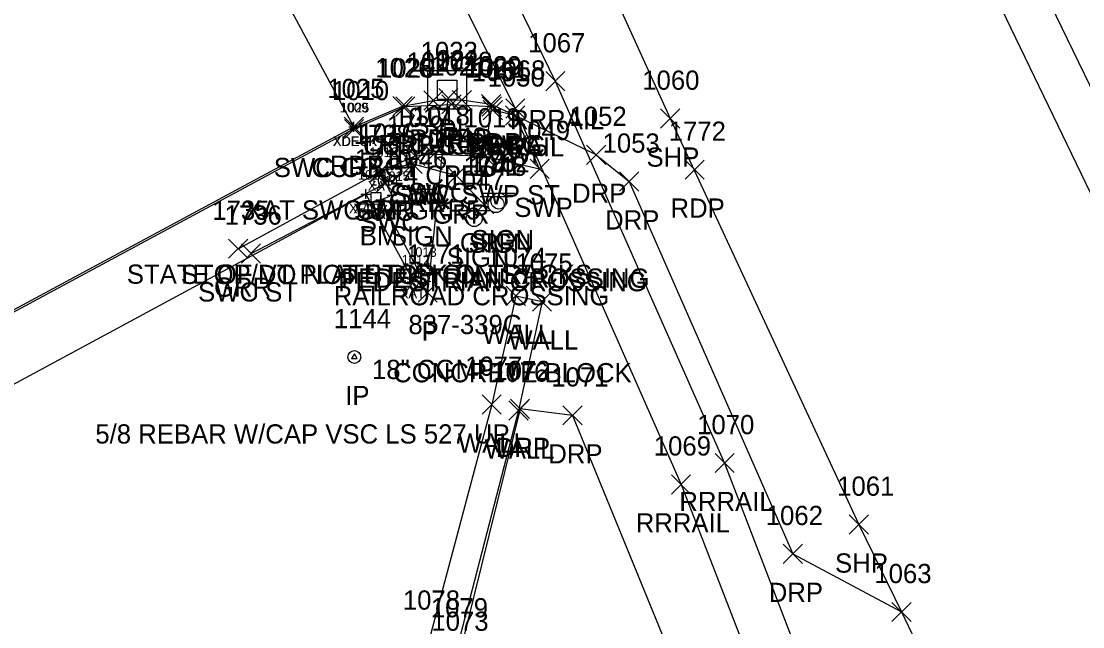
# Model space of a CAD drawing. Extents: x 1635588 to 1637550, y 621583 to 623638.
# Drawn here: x 1636369.1 to 1636479.5, y 623114.4 to 623177.4 of the extents above; entities that cross this region are included whole.
import ezdxf

# ---------------------------------------------------------------- set-up
doc = ezdxf.new("R2010")
doc.units = 0
for name, color, linetype in [('B_A', 7, 'Continuous'), ('B_I', 7, 'Continuous'), ('B_TIC', 7, 'Continuous'), ('BELB', 7, 'Continuous'), ('BF', 7, 'Continuous'), ('BSUBM', 7, 'Continuous'), ('C_A', 7, 'Continuous'), ('C_C', 7, 'Continuous'), ('C_I', 7, 'Continuous'), ('CPBM', 7, 'Continuous'), ('D_A', 7, 'Continuous'), ('D_C', 7, 'Continuous'), ('D_I', 7, 'Continuous'), ('D_TIC', 7, 'Continuous'), ('DCP', 7, 'Continuous'), ('DS', 7, 'Continuous'), ('L_A', 7, 'Continuous'), ('L_C', 7, 'Continuous'), ('L_I', 7, 'Continuous'), ('L_TIC', 7, 'Continuous'), ('LW', 7, 'Continuous'), ('M_A', 7, 'Continuous'), ('M_C', 7, 'Continuous'), ('M_I', 7, 'Continuous'), ('MPIR', 7, 'Continuous'), ('P_A', 7, 'Continuous'), ('P_I', 7, 'Continuous'), ('P_TIC', 7, 'Continuous'), ('PET', 7, 'Continuous'), ('PSP', 7, 'Continuous'), ('R_A', 7, 'Continuous'), ('R_I', 7, 'Continuous'), ('R_TIC', 7, 'Continuous'), ('RC', 7, 'Continuous'), ('RDP', 7, 'Continuous'), ('RGR', 7, 'Continuous'), ('RR', 7, 'Continuous'), ('RSW', 7, 'Continuous'), ('S_A', 7, 'Continuous'), ('S_C', 7, 'Continuous'), ('S_I', 7, 'Continuous'), ('SSGN', 7, 'Continuous')]:
    doc.layers.add(name, color=color, linetype=linetype)

msp = doc.modelspace()

# ---------------------------------------------------------------- linework, layer by layer
at = {"layer": 'B_TIC'}
for p, q in [((1636403.65, 623166.46), (1636403.73, 623166.46)), ((1636403.7, 623166.44), (1636403.77, 623166.44)), ((1636406.44, 623161.8), (1636406.51, 623161.8)), ((1636404.94, 623159.45), (1636405.01, 623159.45)), ((1636404.94, 623159.45), (1636405.01, 623159.45)), ((1636406.48, 623158.84), (1636406.56, 623158.84)), ((1636407.65, 623159.32), (1636407.72, 623159.32)), ((1636409.78, 623150.62), (1636409.85, 623150.62)), ((1636410.45, 623151.42), (1636410.52, 623151.42))]:
    msp.add_line(p, q, dxfattribs=at)
for points in [[(1636403.15, 623166.46), (1636404.15, 623166.46)], [(1636403.19, 623166.44), (1636404.19, 623166.44)], [(1636403.65, 623165.96), (1636403.65, 623166.96)], [(1636403.69, 623165.94), (1636403.69, 623166.94)], [(1636405.93, 623161.8), (1636406.93, 623161.8)], [(1636406.43, 623161.3), (1636406.43, 623162.3)], [(1636404.43, 623159.45), (1636405.43, 623159.45)], [(1636404.43, 623159.45), (1636405.43, 623159.45)], [(1636404.93, 623158.95), (1636404.93, 623159.95)], [(1636404.93, 623158.95), (1636404.93, 623159.95)], [(1636407.64, 623158.82), (1636407.64, 623159.82)], [(1636405.98, 623158.84), (1636406.98, 623158.84)], [(1636406.48, 623158.34), (1636406.48, 623159.34)], [(1636407.14, 623159.32), (1636408.14, 623159.32)], [(1636410.44, 623150.92), (1636410.44, 623151.92)], [(1636409.27, 623150.62), (1636410.27, 623150.62)], [(1636409.77, 623150.12), (1636409.77, 623151.12)], [(1636409.94, 623151.42), (1636410.94, 623151.42)]]:
    msp.add_lwpolyline(points, dxfattribs=at)
at = {"layer": 'BELB'}
msp.add_lwpolyline([(1636339.78, 623132.09), (1636403.65, 623166.46), (1636403.69, 623166.44), (1636388.52, 623194.68), (1636325.04, 623160.46), (1636339.78, 623132.09)], dxfattribs=at)
at = {"layer": 'BF'}
msp.add_lwpolyline([(1636345.01, 623127.11), (1636404.93, 623159.45)], dxfattribs=at)
at = {"layer": 'BSUBM'}
msp.add_lwpolyline([(1636404.93, 623159.45), (1636409.77, 623150.62), (1636410.44, 623151.42), (1636406.48, 623158.84), (1636407.64, 623159.32), (1636406.43, 623161.8)], dxfattribs=at)
at = {"layer": 'CPBM'}
for p, q in [((1636405.48, 623158.62), (1636405.48, 623159.62)), ((1636405.48, 623159.62), (1636406.48, 623159.62)), ((1636406.48, 623159.62), (1636406.48, 623158.62)), ((1636406.48, 623158.62), (1636405.48, 623158.62)), ((1636405.99, 623159.12), (1636405.99, 623159.12)), ((1636405.99, 623159.12), (1636405.99, 623159.12))]:
    msp.add_line(p, q, dxfattribs=at)
at = {"layer": 'D_TIC'}
for points in [[(1636412.52, 623168.43), (1636414.52, 623170.43)], [(1636414.52, 623168.43), (1636412.52, 623170.43)], [(1636410.37, 623148.21), (1636412.37, 623150.21)], [(1636412.37, 623148.21), (1636410.37, 623150.21)]]:
    msp.add_lwpolyline(points, dxfattribs=at)
at = {"layer": 'DCP'}
msp.add_lwpolyline([(1636411.37, 623149.21), (1636413.52, 623169.43)], dxfattribs=at)
at = {"layer": 'DS'}
for p, q in [((1636411.4, 623172.29), (1636415.4, 623172.29)), ((1636411.4, 623168.29), (1636411.4, 623172.29)), ((1636415.4, 623172.29), (1636415.4, 623168.29)), ((1636412.4, 623169.29), (1636412.4, 623171.29)), ((1636412.4, 623171.29), (1636414.4, 623171.29)), ((1636414.4, 623171.29), (1636414.4, 623169.29)), ((1636413.41, 623170.29), (1636413.41, 623170.29)), ((1636413.41, 623170.29), (1636413.41, 623170.29)), ((1636415.4, 623168.29), (1636411.4, 623168.29)), ((1636414.4, 623169.29), (1636412.4, 623169.29))]:
    msp.add_line(p, q, dxfattribs=at)
at = {"layer": 'L_TIC'}
for points in [[(1636419.54, 623147.87), (1636421.54, 623149.87)], [(1636421.54, 623147.87), (1636419.54, 623149.87)], [(1636419.54, 623147.87), (1636421.54, 623149.87)], [(1636421.54, 623147.87), (1636419.54, 623149.87)], [(1636422.27, 623147.27), (1636424.27, 623149.27)], [(1636424.27, 623147.27), (1636422.27, 623149.27)], [(1636417.03, 623136.55), (1636419.03, 623138.55)], [(1636419.03, 623136.55), (1636417.03, 623138.55)], [(1636419.81, 623135.93), (1636421.81, 623137.93)], [(1636421.81, 623135.93), (1636419.81, 623137.93)]]:
    msp.add_lwpolyline(points, dxfattribs=at)
at = {"layer": 'LW'}
for points in [[(1636420.54, 623148.87), (1636418.03, 623137.55), (1636411.56, 623113.22), (1636404.7, 623098.83), (1636400.05, 623087.78), (1636398.19, 623078.04), (1636398.21, 623065.41), (1636401.74, 623065.67), (1636429.92, 623068.92)], [(1636420.54, 623148.87), (1636423.27, 623148.27), (1636420.81, 623136.93), (1636414.48, 623112.42), (1636407.16, 623097.43), (1636402.84, 623086.74), (1636400.49, 623078.12), (1636401.25, 623068.42), (1636429.44, 623071.58), (1636429.92, 623068.92)]]:
    msp.add_lwpolyline(points, dxfattribs=at)
at = {"layer": 'MPIR'}
msp.add_lwpolyline([(1636403.74, 623142.83), (1636403.45, 623142.33), (1636404.03, 623142.33)], close=True, dxfattribs=at)
msp.add_circle((1636403.74, 623142.5), 0.667, dxfattribs=at)
at = {"layer": 'P_TIC'}
for points in [[(1636407.75, 623167.6), (1636409.75, 623169.6)], [(1636409.75, 623167.6), (1636407.75, 623169.6)], [(1636410.96, 623168.19), (1636412.96, 623170.19)], [(1636412.96, 623168.19), (1636410.96, 623170.19)], [(1636413.93, 623168.24), (1636415.93, 623170.24)], [(1636415.93, 623168.24), (1636413.93, 623170.24)], [(1636416.98, 623167.8), (1636418.98, 623169.8)], [(1636418.98, 623167.8), (1636416.98, 623169.8)], [(1636435.6, 623166.3), (1636437.6, 623168.3)], [(1636437.6, 623166.3), (1636435.6, 623168.3)], [(1636402.69, 623165.44), (1636404.69, 623167.44)], [(1636404.69, 623165.44), (1636402.69, 623167.44)], [(1636438.15, 623160.99), (1636440.15, 623162.99)], [(1636440.15, 623160.99), (1636438.15, 623162.99)], [(1636455.23, 623124.07), (1636457.23, 623126.07)], [(1636457.23, 623124.07), (1636455.23, 623126.07)], [(1636459.67, 623114.98), (1636461.67, 623116.98)], [(1636461.67, 623114.98), (1636459.67, 623116.98)]]:
    msp.add_lwpolyline(points, dxfattribs=at)
at = {"layer": 'PET'}
for points in [[(1636457.94, 623205.96), (1636503.15, 623112.3), (1636505.74, 623110.41), (1636508.84, 623109.19), (1636510.58, 623108.45)], [(1636403.69, 623166.44), (1636408.75, 623168.6), (1636411.96, 623169.19), (1636414.93, 623169.24), (1636417.98, 623168.8)], [(1636417.98, 623168.8), (1636420.47, 623167.63)]]:
    msp.add_lwpolyline(points, dxfattribs=at)
at = {"layer": 'PSP'}
msp.add_lwpolyline([(1636412.61, 623220.07), (1636436.6, 623167.3), (1636456.23, 623125.07), (1636460.67, 623115.98), (1636475.52, 623084.87), (1636494.51, 623045.42), (1636524.16, 622986.51), (1636530.74, 622972.24), (1636554.07, 622925.3), (1636577.18, 622886.3), (1636601.72, 622847.41), (1636613.46, 622830.09), (1636645.38, 622782.47), (1636700.61, 622698.86), (1636734.28, 622648.07), (1636752.12, 622619.3), (1636752.46, 622616.81), (1636755.34, 622613.42), (1636810.04, 622534.39), (1636855.63, 622465.66), (1636874.76, 622437.49), (1636904.15, 622393.55)], dxfattribs=at)
at = {"layer": 'R_TIC'}
for points in [[(1636423.65, 623170.19), (1636425.65, 623172.19)], [(1636425.65, 623170.19), (1636423.65, 623172.19)], [(1636408.05, 623167.55), (1636410.05, 623169.55)], [(1636410.05, 623167.55), (1636408.05, 623169.55)], [(1636412.84, 623167.78), (1636414.84, 623169.78)], [(1636414.84, 623167.78), (1636412.84, 623169.78)], [(1636417.04, 623167.56), (1636419.04, 623169.56)], [(1636419.04, 623167.56), (1636417.04, 623169.56)], [(1636417.04, 623167.56), (1636419.04, 623169.56)], [(1636419.04, 623167.56), (1636417.04, 623169.56)], [(1636417.16, 623167.19), (1636419.16, 623169.19)], [(1636419.16, 623167.19), (1636417.16, 623169.19)], [(1636419.47, 623166.63), (1636421.47, 623168.63)], [(1636421.47, 623166.63), (1636419.47, 623168.63)], [(1636419.49, 623167.36), (1636421.49, 623169.36)], [(1636421.49, 623167.36), (1636419.49, 623169.36)], [(1636402.7, 623165.22), (1636404.7, 623167.22)], [(1636404.7, 623165.22), (1636402.7, 623167.22)], [(1636402.7, 623165.22), (1636404.7, 623167.22)], [(1636404.7, 623165.22), (1636402.7, 623167.22)], [(1636409.08, 623162.43), (1636411.08, 623164.43)], [(1636411.08, 623162.43), (1636409.08, 623164.43)], [(1636411.01, 623162.61), (1636413.01, 623164.61)], [(1636413.01, 623162.61), (1636411.01, 623164.61)], [(1636416.31, 623162.38), (1636418.31, 623164.38)], [(1636418.31, 623162.38), (1636416.31, 623164.38)], [(1636416.31, 623162.38), (1636418.31, 623164.38)], [(1636418.31, 623162.38), (1636416.31, 623164.38)], [(1636427.9, 623162.54), (1636429.9, 623164.54)], [(1636429.9, 623162.54), (1636427.9, 623164.54)], [(1636405.43, 623160.8), (1636407.43, 623162.8)], [(1636407.43, 623160.8), (1636405.43, 623162.8)], [(1636405.43, 623160.8), (1636407.43, 623162.8)], [(1636407.43, 623160.8), (1636405.43, 623162.8)], [(1636408.81, 623161.6), (1636410.81, 623163.6)], [(1636410.81, 623161.6), (1636408.81, 623163.6)], [(1636422.02, 623161.07), (1636424.02, 623163.07)], [(1636424.02, 623161.07), (1636422.02, 623163.07)], [(1636405.35, 623160.66), (1636407.35, 623162.66)], [(1636407.35, 623160.66), (1636405.35, 623162.66)], [(1636413.35, 623160.37), (1636415.35, 623162.37)], [(1636415.35, 623160.37), (1636413.35, 623162.37)], [(1636431.34, 623159.76), (1636433.34, 623161.76)], [(1636433.34, 623159.76), (1636431.34, 623161.76)], [(1636405.94, 623159.54), (1636407.94, 623161.54)], [(1636407.94, 623159.54), (1636405.94, 623161.54)], [(1636416.24, 623157.38), (1636418.24, 623159.38)], [(1636418.24, 623157.38), (1636416.24, 623159.38)], [(1636390.66, 623152.77), (1636392.66, 623154.77)], [(1636392.66, 623152.77), (1636390.66, 623154.77)], [(1636391.99, 623152.27), (1636393.99, 623154.27)], [(1636393.99, 623152.27), (1636391.99, 623154.27)], [(1636419.98, 623136.1), (1636421.98, 623138.1)], [(1636421.98, 623136.1), (1636419.98, 623138.1)], [(1636425.44, 623135.43), (1636427.44, 623137.43)], [(1636427.44, 623135.43), (1636425.44, 623137.43)], [(1636425.44, 623135.43), (1636427.44, 623137.43)], [(1636427.44, 623135.43), (1636425.44, 623137.43)], [(1636441.27, 623130.47), (1636443.27, 623132.47)], [(1636443.27, 623130.47), (1636441.27, 623132.47)], [(1636436.73, 623128.25), (1636438.73, 623130.25)], [(1636438.73, 623128.25), (1636436.73, 623130.25)], [(1636448.37, 623121.02), (1636450.37, 623123.02)], [(1636450.37, 623121.02), (1636448.37, 623123.02)], [(1636459.67, 623114.98), (1636461.67, 623116.98)], [(1636461.67, 623114.98), (1636459.67, 623116.98)]]:
    msp.add_lwpolyline(points, dxfattribs=at)
at = {"layer": 'RC'}
msp.add_lwpolyline([(1636403.7, 623166.22), (1636409.05, 623168.55), (1636413.84, 623168.78), (1636418.04, 623168.56)], dxfattribs=at)
at = {"layer": 'RDP'}
for points in [[(1636428.9, 623163.54), (1636420.47, 623167.63)], [(1636428.9, 623163.54), (1636432.34, 623160.76), (1636449.37, 623122.02), (1636460.67, 623115.98)], [(1636426.44, 623136.43), (1636420.98, 623137.1), (1636414.54, 623111.02), (1636407.75, 623097.32), (1636403.36, 623087.01), (1636401.25, 623078.34), (1636401.37, 623068.48), (1636429.73, 623071.8), (1636430.14, 623068.89), (1636406.01, 623065.32), (1636405.81, 623063.86), (1636404.22, 622946.58), (1636428.1, 622945.11), (1636429.15, 622942.89), (1636426.11, 622934.05), (1636419.92, 622924.84), (1636405.51, 622913.03), (1636421.18, 622869.94), (1636453.55, 622783.03), (1636469.62, 622787.52)], [(1636426.44, 623136.43), (1636451, 623076.46), (1636452.49, 623074.67), (1636454.25, 623073.68), (1636457.22, 623073.34), (1636458.96, 623074.5), (1636462.36, 623079.17)]]:
    msp.add_lwpolyline(points, dxfattribs=at)
at = {"layer": 'RGR'}
for points in [[(1636391.66, 623153.77), (1636406.43, 623161.8)], [(1636409.81, 623162.6), (1636406.43, 623161.8)], [(1636409.81, 623162.6), (1636414.35, 623161.37), (1636417.24, 623158.38)]]:
    msp.add_lwpolyline(points, dxfattribs=at)
at = {"layer": 'RR'}
for points in [[(1636406.43, 623208.62), (1636424.65, 623171.19), (1636442.27, 623131.47), (1636462.36, 623079.17), (1636475.1, 623045.34), (1636499.5, 622979.8), (1636509.41, 622950.55), (1636516.07, 622929.71), (1636530.2, 622882.11), (1636568.93, 622740.93), (1636580.62, 622697.82)], [(1636401.96, 623205.78), (1636420.49, 623168.36), (1636437.73, 623129.25), (1636458.96, 623074.5), (1636470.76, 623043.73), (1636495.27, 622977.34), (1636504.04, 622950.72), (1636511.18, 622928.71), (1636525.38, 622880.65), (1636564.25, 622739.19), (1636576, 622696.58)]]:
    msp.add_lwpolyline(points, dxfattribs=at)
at = {"layer": 'RSW'}
for points in [[(1636462.26, 623207.84), (1636507.51, 623114.66)], [(1636406.43, 623161.8), (1636410.08, 623163.43), (1636412.01, 623163.61), (1636417.31, 623163.38), (1636418.04, 623168.56)], [(1636417.31, 623163.38), (1636423.02, 623162.07), (1636420.47, 623167.63), (1636418.16, 623168.19)], [(1636342.86, 623126.05), (1636339.68, 623131.82), (1636403.7, 623166.22)], [(1636392.99, 623153.27), (1636406.94, 623160.54), (1636406.35, 623161.66)]]:
    msp.add_lwpolyline(points, dxfattribs=at)
at = {"layer": 'SSGN'}
for p, q in [((1636408.65, 623159.95), (1636411.98, 623159.95)), ((1636417.13, 623159.56), (1636420.46, 623159.56)), ((1636410.3, 623159.12), (1636410.3, 623159.12)), ((1636416.84, 623159.19), (1636420.18, 623159.19)), ((1636418.49, 623158.36), (1636418.49, 623158.36)), ((1636418.78, 623158.73), (1636418.78, 623158.73)), ((1636414.57, 623157.73), (1636417.9, 623157.73)), ((1636416.21, 623156.9), (1636416.21, 623156.9))]:
    msp.add_line(p, q, dxfattribs=at)
for centre in [(1636410.3, 623159.12), (1636418.78, 623158.73), (1636418.49, 623158.36), (1636416.21, 623156.9)]:
    msp.add_circle(centre, 0.833, dxfattribs=at)

# ---------------------------------------------------------------- texts
at = {"layer": 'B_A'}
for s, p in [('XDECK', (1636401.49, 623164.46)), ('XDECK', (1636401.53, 623164.44)), ('XAT', (1636405.14, 623159.8)), ('XFAT', (1636403.19, 623157.45)), ('XAT', (1636403.64, 623157.45)), ('XAT', (1636406.35, 623157.32)), ('XAT', (1636405.19, 623156.84)), ('XAT', (1636408.48, 623148.62)), ('XAT', (1636409.15, 623149.42))]:
    msp.add_text(s, height=1, dxfattribs=at).set_placement(p)
at = {"layer": 'B_I'}
for s, p in [('1009', (1636402.22, 623167.96)), ('1025', (1636402.31, 623167.94)), ('1016', (1636405.3, 623163.3)), ('1011', (1636404.11, 623160.95)), ('1011', (1636404.11, 623160.95)), ('1015', (1636406.54, 623160.82)), ('1014', (1636405.38, 623160.34)), ('1013', (1636409.34, 623152.92)), ('1012', (1636408.67, 623152.12))]:
    msp.add_text(s, height=1, dxfattribs=at).set_placement(p)
at = {"layer": 'C_A'}
msp.add_text('BM', height=2, dxfattribs=at).set_placement((1636404.3, 623154.12))
at = {"layer": 'C_C'}
msp.add_text('STATE OF VT PLATE DISK ON ST.', height=2, dxfattribs=at).set_placement((1636380.07, 623150.12))
at = {"layer": 'C_I'}
msp.add_text('1710', height=2, dxfattribs=at).set_placement((1636403.78, 623162.12))
at = {"layer": 'D_A'}
for s, p in [('DI', (1636412.46, 623165.29)), ('P', (1636412.89, 623164.43)), ('P', (1636410.75, 623144.21))]:
    msp.add_text(s, height=2, dxfattribs=at).set_placement(p)
at = {"layer": 'D_C'}
for s, p in [('24 CPEP', (1636407.41, 623160.43)), ('18" CGMP', (1636405.58, 623140.21))]:
    msp.add_text(s, height=2, dxfattribs=at).set_placement(p)
at = {"layer": 'D_I'}
for s, p in [('1023', (1636410.64, 623173.29)), ('1024', (1636410.75, 623172.43)), ('1771', (1636409.25, 623152.21))]:
    msp.add_text(s, height=2, dxfattribs=at).set_placement(p)
at = {"layer": 'L_A'}
for p in [(1636417.03, 623143.87), (1636417.03, 623143.87), (1636419.76, 623143.27), (1636414.52, 623132.55), (1636417.29, 623131.93)]:
    msp.add_text('WALL', height=2, dxfattribs=at).set_placement(p)
at = {"layer": 'L_C'}
msp.add_text('CONCRETE BLOCK', height=2, dxfattribs=at).set_placement((1636407.78, 623139.87))
msp.add_text('CONCRETE BLOCK', height=2, dxfattribs=at).set_placement((1636407.78, 623139.87))
at = {"layer": 'L_I'}
for s, p in [('1074', (1636417.77, 623151.87)), ('1074', (1636417.77, 623151.87)), ('1075', (1636420.5, 623151.27)), ('1077', (1636415.26, 623140.55)), ('1076', (1636417.98, 623139.93)), ('1078', (1636408.79, 623116.22)), ('1079', (1636411.7, 623115.42))]:
    msp.add_text(s, height=2, dxfattribs=at).set_placement(p)
at = {"layer": 'M_A'}
msp.add_text('IP', height=2, dxfattribs=at).set_placement((1636402.79, 623137.5))
at = {"layer": 'M_C'}
msp.add_text('5/8 REBAR W/CAP VSC LS 527 UP', height=2, dxfattribs=at).set_placement((1636376.79, 623133.5))
at = {"layer": 'M_I'}
msp.add_text('1144', height=2, dxfattribs=at).set_placement((1636401.61, 623145.5))
at = {"layer": 'P_A'}
for s, p in [('RDP', (1636409.44, 623164.19)), ('RDP', (1636412.42, 623164.24)), ('RDP', (1636406.24, 623163.6)), ('RDP', (1636415.47, 623163.8)), ('SHP', (1636434.14, 623162.3)), ('RDP', (1636401.18, 623161.44)), ('RDP', (1636436.64, 623156.99)), ('SHP', (1636453.76, 623120.07))]:
    msp.add_text(s, height=2, dxfattribs=at).set_placement(p)
at = {"layer": 'P_I'}
for s, p in [('1027', (1636409.18, 623172.19)), ('1028', (1636412.16, 623172.24)), ('1029', (1636415.2, 623171.8)), ('1026', (1636405.92, 623171.6)), ('1060', (1636433.7, 623170.3)), ('1025', (1636400.92, 623169.44)), ('1772', (1636436.45, 623164.99)), ('1061', (1636453.98, 623128.07)), ('1063', (1636457.85, 623118.98))]:
    msp.add_text(s, height=2, dxfattribs=at).set_placement(p)
at = {"layer": 'R_A'}
for s, p in [('RRRAIL', (1636419.94, 623166.19)), ('CURBG', (1636404.64, 623163.55)), ('CURBG', (1636409.42, 623163.78)), ('CG SWC', (1636412.57, 623163.56)), ('CURBG', (1636413.63, 623163.56)), ('SWP', (1636415.52, 623163.19)), ('RRRAIL', (1636415.78, 623163.36)), ('SWP', (1636417.83, 623162.63)), ('SWC CG ST', (1636395.36, 623161.22)), ('CURBG', (1636399.28, 623161.22)), ('SWC', (1636409.37, 623158.61)), ('DRP', (1636426.39, 623158.54)), ('GRR', (1636407.3, 623157.6)), ('SWC', (1636407.44, 623158.43)), ('SWC SWP ST', (1636407.9, 623158.38)), ('SWC SWP ST', (1636407.9, 623158.38)), ('XAT SWC ST GRR5', (1636392.34, 623156.8)), ('SWC', (1636403.71, 623156.66)), ('GRR', (1636403.92, 623156.8)), ('GRR', (1636411.84, 623156.37)), ('SWP', (1636420.38, 623157.07)), ('SWC', (1636404.31, 623155.54)), ('DRP', (1636429.83, 623155.76)), ('GRR', (1636414.72, 623153.38)), ('GRR', (1636389.14, 623148.77)), ('SWC ST', (1636387.48, 623148.27)), ('DRP', (1636418.46, 623132.1)), ('DRP', (1636423.92, 623131.43)), ('DRP', (1636423.92, 623131.43)), ('RRRAIL', (1636437.56, 623126.47)), ('RRRAIL', (1636433.02, 623124.25)), ('DRP', (1636446.86, 623117.02))]:
    msp.add_text(s, height=2, dxfattribs=at).set_placement(p)
at = {"layer": 'R_I'}
for s, p in [('1067', (1636421.83, 623174.19)), ('1021', (1636411.64, 623171.78)), ('1020', (1636406.2, 623171.55)), ('1022', (1636415.27, 623171.56)), ('1022', (1636415.27, 623171.56)), ('1051', (1636415.96, 623171.19)), ('1068', (1636417.67, 623171.36)), ('1050', (1636417.61, 623170.63)), ('1010', (1636401.41, 623169.22)), ('1010', (1636401.41, 623169.22)), ('1017', (1636407.88, 623166.43)), ('1018', (1636409.81, 623166.61)), ('1019', (1636415.1, 623166.38)), ('1019', (1636415.1, 623166.38)), ('1052', (1636426.13, 623166.54)), ('1739', (1636407.11, 623165.6)), ('1738', (1636403.66, 623164.66)), ('1016', (1636404.18, 623164.8)), ('1016', (1636404.18, 623164.8)), ('1740', (1636411.57, 623164.37)), ('1049', (1636420.24, 623165.07)), ('1737', (1636404.25, 623163.54)), ('1053', (1636429.57, 623163.76)), ('1741', (1636415.11, 623161.38)), ('1735', (1636388.96, 623156.77)), ('1736', (1636390.24, 623156.27)), ('1072', (1636418.21, 623140.1)), ('1071', (1636424.23, 623139.43)), ('1071', (1636424.23, 623139.43)), ('1070', (1636439.41, 623134.47)), ('1069', (1636434.9, 623132.25)), ('1062', (1636446.55, 623125.02)), ('1063', (1636457.85, 623118.98)), ('1073', (1636411.76, 623114.02))]:
    msp.add_text(s, height=2, dxfattribs=at).set_placement(p)
at = {"layer": 'S_A'}
for p in [(1636407.44, 623154.1), (1636415.63, 623153.34), (1636415.92, 623153.71), (1636413.35, 623151.88)]:
    msp.add_text('SIGN', height=2, dxfattribs=at).set_placement(p)
at = {"layer": 'S_C'}
for s, p in [('STOP/DO NOT STOP ON TRACKS', (1636385.68, 623150.1)), ('PEDESTRIAN CROSSING', (1636402.36, 623149.71)), ('PEDESTRIAN CROSSING', (1636402.07, 623149.34)), ('RAILROAD CROSSING', (1636401.6, 623147.88)), ('837-339G', (1636409.37, 623144.88))]:
    msp.add_text(s, height=2, dxfattribs=at).set_placement(p)
at = {"layer": 'S_I'}
for s, p in [('1046', (1636407.45, 623162.1)), ('1048', (1636415.7, 623161.34)), ('1762', (1636416.02, 623161.71)), ('1047', (1636413.42, 623159.88))]:
    msp.add_text(s, height=2, dxfattribs=at).set_placement(p)

doc.saveas('drawing.dxf')
